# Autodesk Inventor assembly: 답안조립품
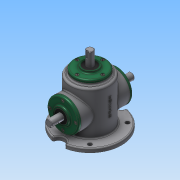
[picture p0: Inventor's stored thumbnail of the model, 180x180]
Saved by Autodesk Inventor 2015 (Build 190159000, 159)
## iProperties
Created: 2018-04
Part Number: 답안조립품
Document SubType Name: Assembly
Designer: SCD-A04
Author: SCD-A04
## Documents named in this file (16)
- C:\Users\SCD-A04\Desktop\480408V1002\답안조립품.iam
- C:\Users\SCD-A04\Desktop\480408V1002\본체.ipt
- C:\Users\SCD-A04\Desktop\480408V1002\메인 베벨기어.ipt
- C:\Users\SCD-A04\Desktop\480408V1002\메인 축.ipt
- 메인 축.ipt
- C:\Users\SCD-A04\Desktop\480408V1002\베어링 6203.ipt
- C:\Users\SCD-A04\Desktop\480408V1002\볼트 M4.ipt
- 볼트 M4.ipt
- C:\Users\SCD-A04\Desktop\480408V1002\서브 베벨기어.ipt
- C:\Users\SCD-A04\Desktop\480408V1002\서브 축.ipt
- 서브 축.ipt
- C:\Users\SCD-A04\Desktop\480408V1002\오일 실.ipt
- 오일 실.ipt
- C:\Users\SCD-A04\Desktop\480408V1002\커버.ipt
- C:\Users\SCD-A04\Desktop\480408V1002\키 4x4.ipt
- C:\Users\SCD-A04\Desktop\480408V1002\키 5x5.ipt
